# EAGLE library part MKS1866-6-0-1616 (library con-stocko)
Serie MKS 1850 Lötstifte In-line, Raster 2.5 mm, Stiftwannen, stehend, mit Rastlasche Source: http://www.stocko.de/de/index.php?seite=ka_rfk2_mks1850.html&rubrik=Katalog+-+RFK+2 rfk_1850.pdf
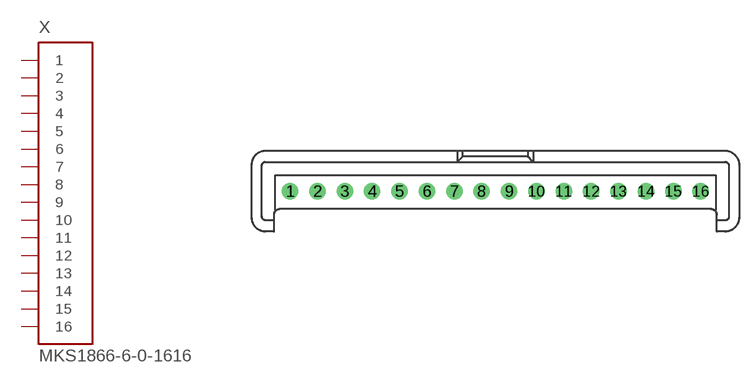
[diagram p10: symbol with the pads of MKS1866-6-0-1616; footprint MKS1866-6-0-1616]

Designator prefix X

## MKS1866-6-0-1616 (OC_FARNELL: unknown; OC_NEWARK: unknown)  [MKS1866-6-0-1616]
1  1  in
2  2  in
3  3  in
4  4  in
5  5  in
6  6  in
7  7  in
8  8  in
9  9  in
10  10  in
11  11  in
12  12  in
13  13  in
14  14  in
15  15  in
16  16  in

## Footprint MKS1866-6-0-1616 (pad centres in mm)
Serie MKS 1850 Lötstifte In-line, Raster 2.5 mm, Stiftwannen, stehend, mit Rastlasche Source: http://www.stocko.de/de/index.php?seite=ka_rfk2_mks1850.html&rubrik=Katalog+-+RFK+2 rfk_1850.pdf
drill 1 pad 1.422 round: 1 -18.75,0; 2 -16.25,0; 3 -13.75,0; 4 -11.25,0; 5 -8.75,0; 6 -6.25,0; 7 -3.75,0; 8 -1.25,0; 9 1.25,0; 10 3.75,0; 11 6.25,0; 12 8.75,0; 13 11.25,0; 14 13.75,0; 15 16.25,0; 16 18.75,0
